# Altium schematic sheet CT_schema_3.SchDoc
size 493 x 398 mm
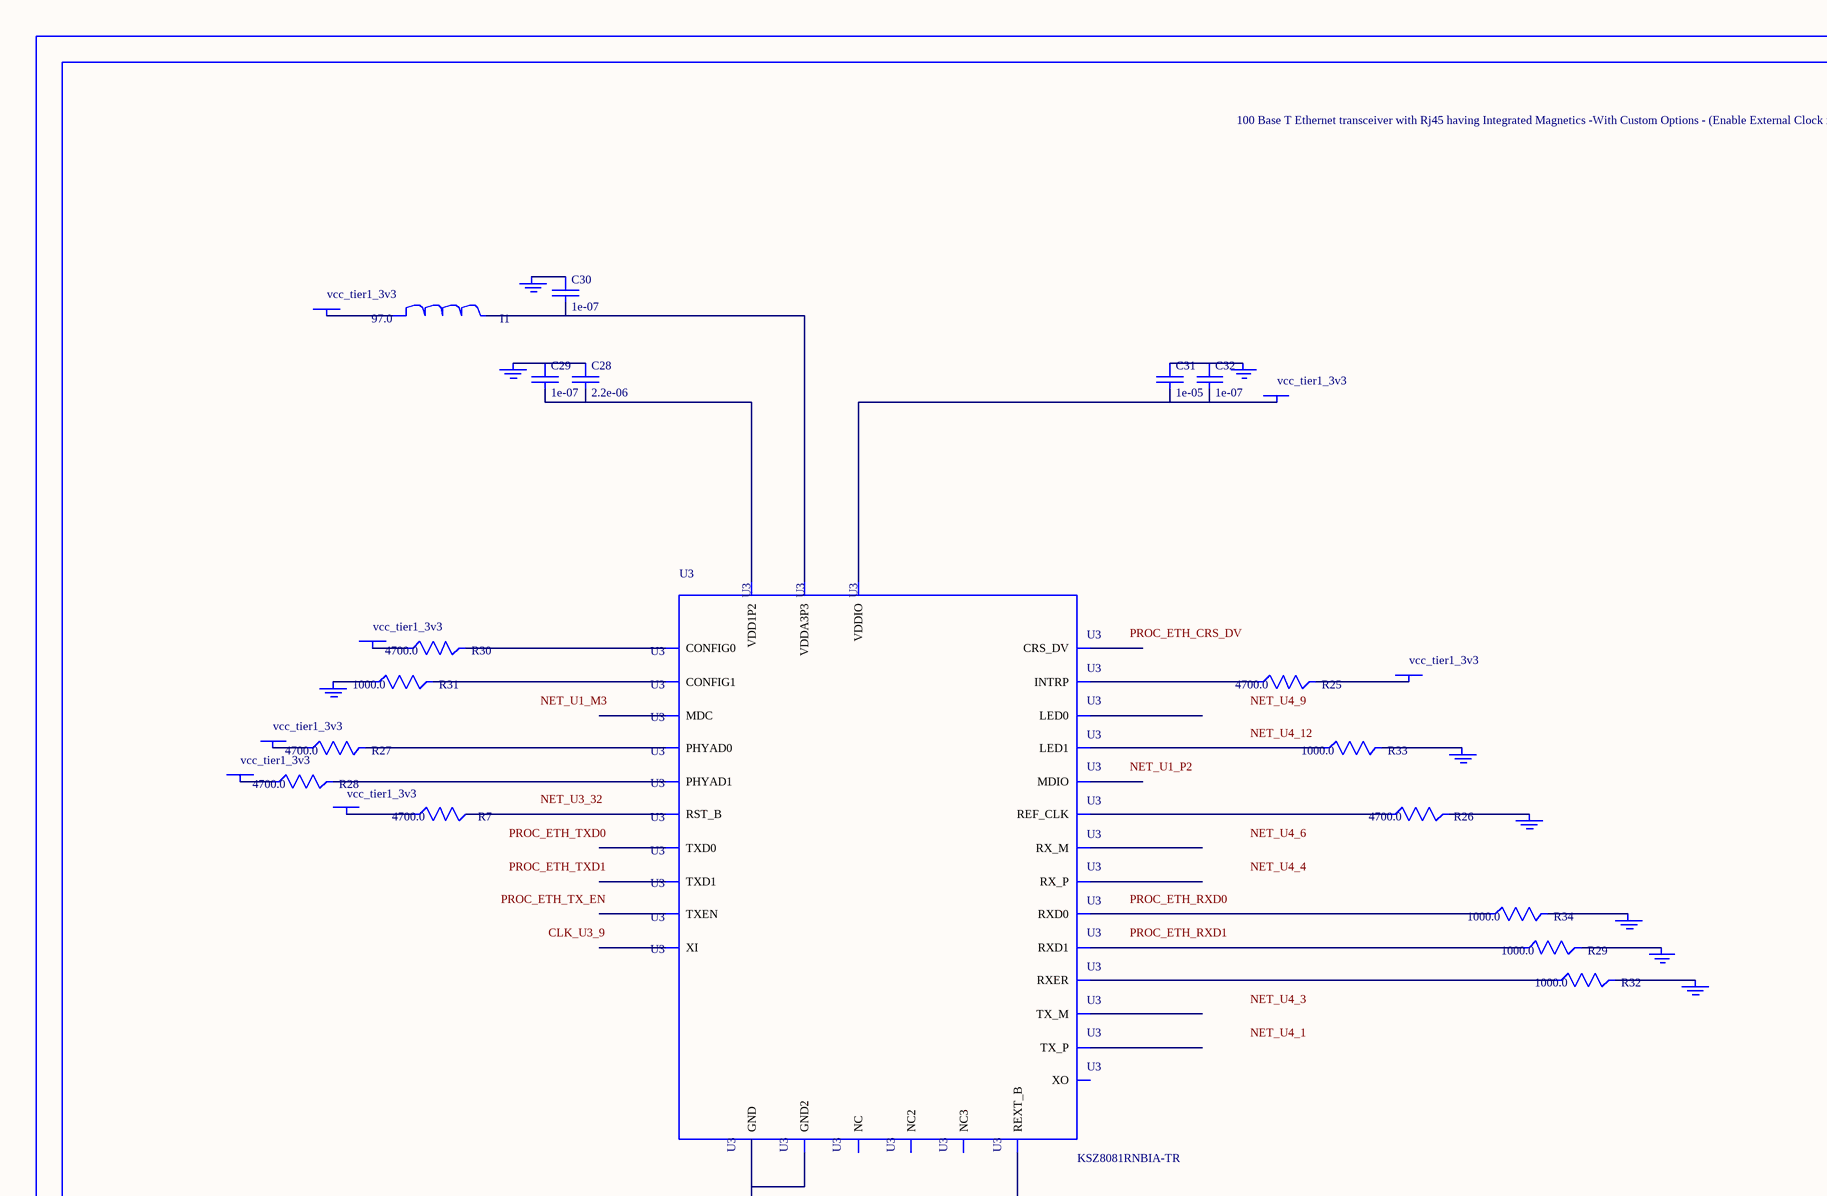
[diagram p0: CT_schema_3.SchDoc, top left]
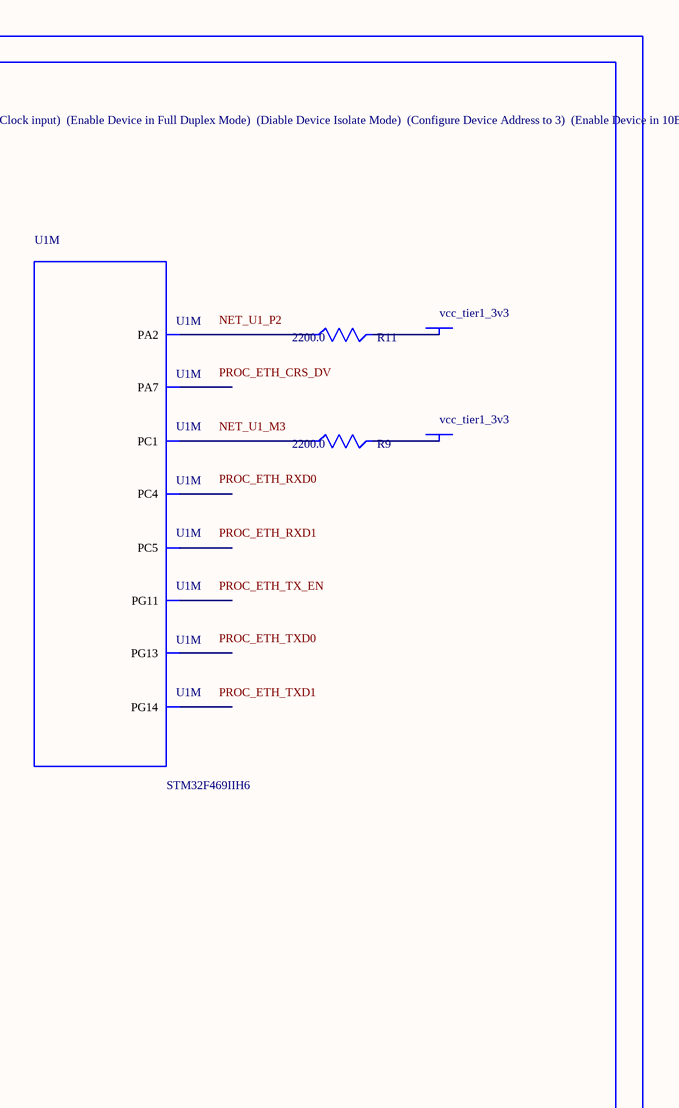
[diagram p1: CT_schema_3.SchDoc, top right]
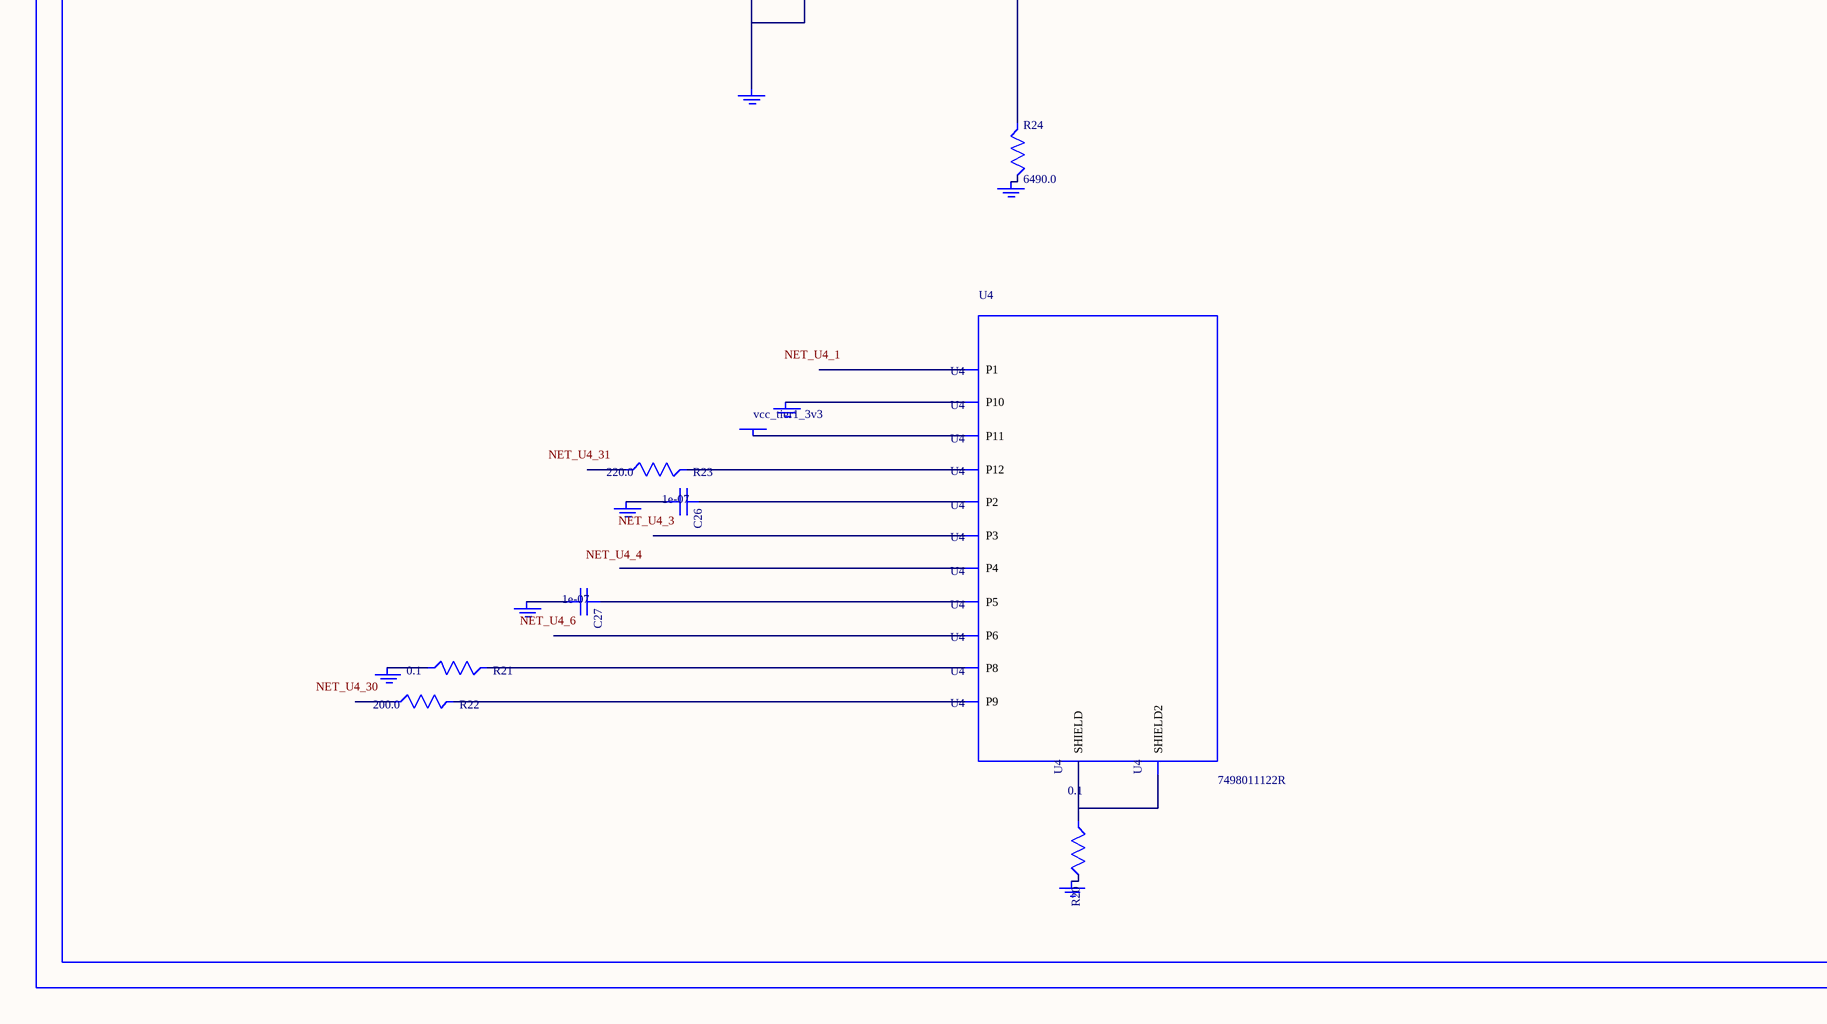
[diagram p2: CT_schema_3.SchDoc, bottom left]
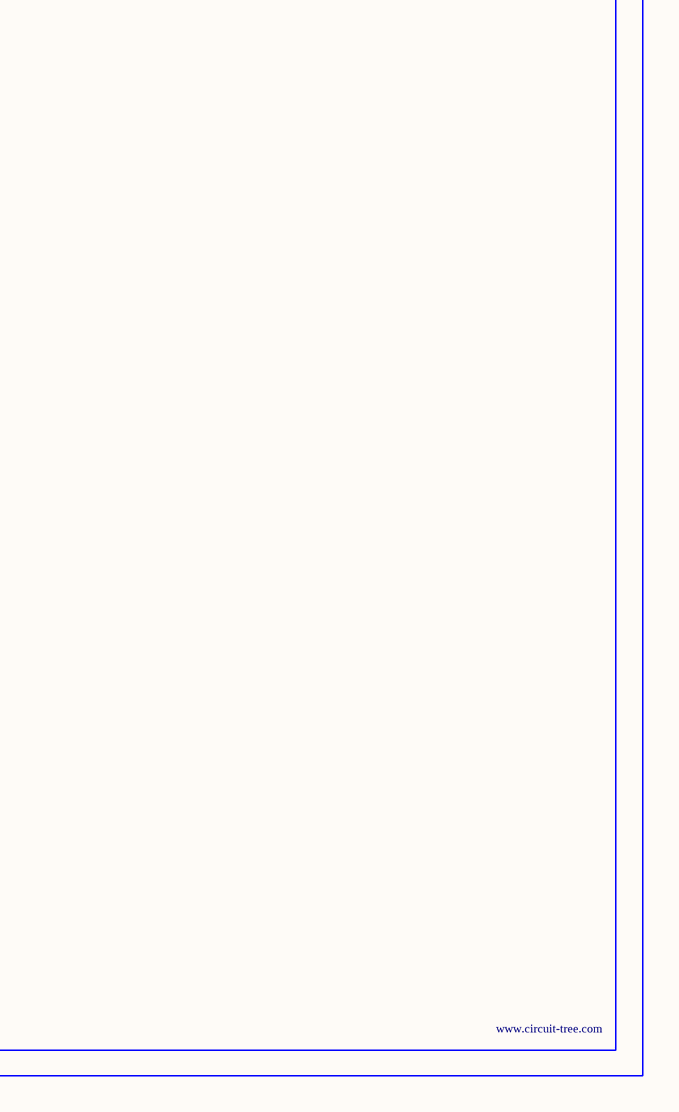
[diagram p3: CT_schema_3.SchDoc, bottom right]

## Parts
BORDER2  (no value)
C26  1e-07  [C0402]
C27  1e-07  [C0402]
C28  2.2e-06  [C0603]
C29  1e-07  [C0402]
C30  1e-07  [C0402]
C31  1e-05  [C0805]
C32  1e-07  [C0402]
GND_INSTANCE_2_0  (no value)
GND_INSTANCE_2_1  (no value)
GND_INSTANCE_2_2  (no value)
GND_INSTANCE_2_3  (no value)
GND_INSTANCE_2_4  (no value)
GND_INSTANCE_2_5  (no value)
GND_INSTANCE_2_6  (no value)
GND_INSTANCE_2_7  (no value)
GND_INSTANCE_2_8  (no value)
GND_INSTANCE_2_9  (no value)
GND_INSTANCE_2_10  (no value)
GND_INSTANCE_2_11  (no value)
GND_INSTANCE_2_12  (no value)
GND_INSTANCE_2_13  (no value)
GND_INSTANCE_2_14  (no value)
GND_INSTANCE_2_15  (no value)
I1  97.0  [R0603]
POWER_INSTANCE_2_0  vcc_tier1_3v3
POWER_INSTANCE_2_1  vcc_tier1_3v3
POWER_INSTANCE_2_2  vcc_tier1_3v3
POWER_INSTANCE_2_3  vcc_tier1_3v3
POWER_INSTANCE_2_4  vcc_tier1_3v3
POWER_INSTANCE_2_5  vcc_tier1_3v3
POWER_INSTANCE_2_6  vcc_tier1_3v3
POWER_INSTANCE_2_7  vcc_tier1_3v3
POWER_INSTANCE_2_8  vcc_tier1_3v3
POWER_INSTANCE_2_9  vcc_tier1_3v3
R7  4700.0  [R0603]
R9  2200.0  [R0603]
R11  2200.0  [R0603]
R20  0.1  [R0603]
R21  0.1  [R0603]
R22  200.0  [R0603]
R23  220.0  [R0603]
R24  6490.0  [R0603]
R25  4700.0  [R0603]
R26  4700.0  [R0603]
R27  4700.0  [R0603]
R28  4700.0  [R0603]
R29  1000.0  [R0603]
R30  4700.0  [R0603]
R31  1000.0  [R0603]
R32  1000.0  [R0603]
R33  1000.0  [R0603]
R34  1000.0  [R0603]
U1  STM32F469IIH6  [UFBGA176]  (part M of 17)
U3  KSZ8081RNBIA-TR  [QFN-32]
U4  7498011122R  [7498011122R]

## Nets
NetC26_1: C26.1 U4.2(P2)
NetC26_2: C26.2 GND_INSTANCE_2_11.0(GND)
NetC27_1: C27.1 U4.5(P5)
NetC27_2: C27.2 GND_INSTANCE_2_12.0(GND)
NetC28_1: C28.1 C29.1 GND_INSTANCE_2_0.0(GND)
NetC28_2: C28.2 C29.2 U3.2(VDD1P2)
NetC30_1: C30.1 GND_INSTANCE_2_1.0(GND)
NetC30_2: C30.2 I1.2 U3.3(VDDA3P3)
NetC31_1: C31.1 C32.1 GND_INSTANCE_2_5.0(GND)
NetC31_2: C31.2 C32.2 POWER_INSTANCE_2_3.0(PWR) U3.17(VDDIO)
NetGND_INSTANCE_2_2_0: GND_INSTANCE_2_2.0(GND) R24.2
NetGND_INSTANCE_2_3_0: GND_INSTANCE_2_3.0(GND) R29.2
NetGND_INSTANCE_2_4_0: GND_INSTANCE_2_4.0(GND) R34.2
NetGND_INSTANCE_2_6_0: GND_INSTANCE_2_6.0(GND) R26.2
NetGND_INSTANCE_2_7_0: GND_INSTANCE_2_7.0(GND) R32.2
NetGND_INSTANCE_2_8_0: GND_INSTANCE_2_8.0(GND) R31.1
NetGND_INSTANCE_2_9_0: GND_INSTANCE_2_9.0(GND) R33.2
NetGND_INSTANCE_2_10_0: GND_INSTANCE_2_10.0(GND) U3.1(GND) U3.EXP(GND2)
NetGND_INSTANCE_2_13_0: GND_INSTANCE_2_13.0(GND) R21.1
NetGND_INSTANCE_2_14_0: GND_INSTANCE_2_14.0(GND) U4.10(P10)
NetGND_INSTANCE_2_15_0: GND_INSTANCE_2_15.0(GND) R20.2
NetI1_1: I1.1 POWER_INSTANCE_2_0.0(PWR)
NetPOWER_INSTANCE_2_1_0: POWER_INSTANCE_2_1.0(PWR) R27.1
NetPOWER_INSTANCE_2_2_0: POWER_INSTANCE_2_2.0(PWR) R28.1
NetPOWER_INSTANCE_2_4_0: POWER_INSTANCE_2_4.0(PWR) R25.2
NetPOWER_INSTANCE_2_5_0: POWER_INSTANCE_2_5.0(PWR) R30.1
NetPOWER_INSTANCE_2_6_0: POWER_INSTANCE_2_6.0(PWR) R7.1
NetPOWER_INSTANCE_2_7_0: POWER_INSTANCE_2_7.0(PWR) R11.2
NetPOWER_INSTANCE_2_8_0: POWER_INSTANCE_2_8.0(PWR) R9.2
NetPOWER_INSTANCE_2_9_0: POWER_INSTANCE_2_9.0(PWR) U4.11(P11)
NetR7_2: R7.2 U3.32(RST_B)
NetR9_1: R9.1 U1.M3(PC1)
NetR11_1: R11.1 U1.P2(PA2)
NetR20_1: R20.1 U4.13(SHIELD) U4.14(SHIELD2)
NetR21_2: R21.2 U4.8(P8)
NetR22_2: R22.2 U4.9(P9)
NetR23_2: R23.2 U4.12(P12)
NetR24_1: R24.1 U3.10(REXT_B)
NetR25_1: R25.1 U3.21(INTRP)
NetR26_1: R26.1 U3.19(REF_CLK)
NetR27_2: R27.2 U3.13(PHYAD0)
NetR28_2: R28.2 U3.14(PHYAD1)
NetR29_1: R29.1 U3.15(RXD1)
NetR30_2: R30.2 U3.28(CONFIG0)
NetR31_2: R31.2 U3.29(CONFIG1)
NetR32_1: R32.1 U3.20(RXER)
NetR33_1: R33.1 U3.31(LED1)
NetR34_1: R34.1 U3.16(RXD0)

Not connected (* = marked no-connect by the designer): R22 1; R23 1; U1 A7(PG14) A8(PG13) B9(PG11) N5(PC4) P5(PC5) R3(PA7); U3 4(RX_M) 5(RX_P) 6(TX_M) 7(TX_P) 8(XO) 9(XI) 11(MDIO) 12(MDC) 18(CRS_DV) 22(NC) 23(TXEN) 24(TXD0) 25(TXD1) 26(NC2) 27(NC3) 30(LED0); U4 1(P1) 3(P3) 4(P4) 6(P6)

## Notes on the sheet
- Labels drawn without touching a wire or pin: CLK_U3_9, NET_U1_M3, NET_U1_P2, NET_U3_32, NET_U4_1, NET_U4_3, NET_U4_4, NET_U4_6, NET_U4_9, NET_U4_12, NET_U4_30, NET_U4_31, PROC_ETH_CRS_DV, PROC_ETH_RXD0, PROC_ETH_RXD1, PROC_ETH_TX_EN, PROC_ETH_TXD0, PROC_ETH_TXD1

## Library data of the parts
BORDER2 = BORDER_PAGE2
C26 C27 C29 C30 C32 = C0402C104K3RACTU
C28 = C0603C225K8RACTU
C31 = C0805C106K8RACTU
GND_INSTANCE_2_0-GND_INSTANCE_2_15 = GND
I1 = I1
POWER_INSTANCE_2_0-POWER_INSTANCE_2_9 = PWR
R7 R25-R28 R30 = RC0603JR-074K7L
R9 R11 = RC0603JR-072K2L
R20 R21 = ERJ-3RSFR10V
R22 = RC0603JR-07200RL
R23 = RC0603JR-07220RL
R24 = ERJ-3EKF6491V
R29 R31-R34 = RC0603JR-071KL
